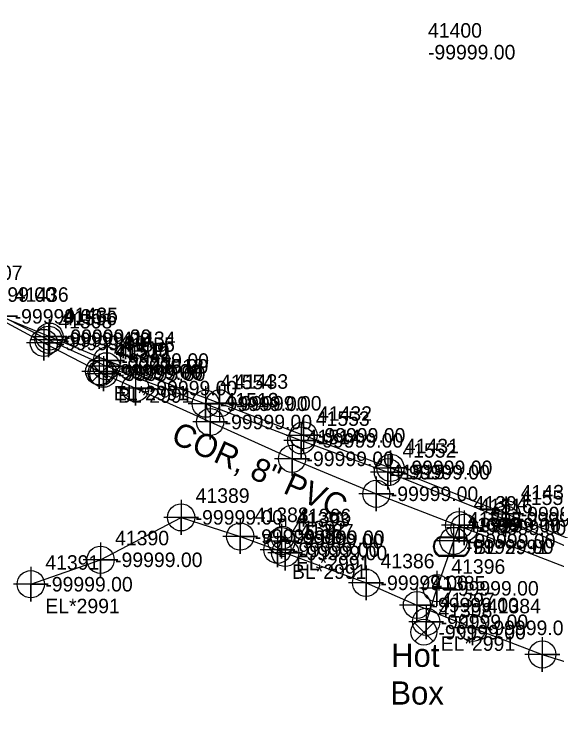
# Model space of a CAD drawing. Extents: x 2083698 to 2094313, y 743246 to 752873.
# Drawn here: x 2091391.9 to 2091485.3, y 744015.4 to 744139.8 of the extents above; entities that cross this region are included whole.
import ezdxf

# ---------------------------------------------------------------- set-up
doc = ezdxf.new("R2010")
doc.units = 0
for name, color, linetype in [('COGO Default Chain', 7, 'Continuous'), ('COGO Default Curve', 7, 'Continuous'), ('COGO Default Point Number', 7, 'Continuous'), ('Default Symbol CELL', 7, 'Continuous'), ('Default Symbol Cogo Comment', 7, 'Continuous'), ('Default Symbol Cogo Number', 7, 'Continuous'), ('Exist Guardrail', 7, 'Continuous'), ('Exist Property Line', 7, 'Continuous'), ('Exist Property Line Leader', 7, 'Continuous'), ('Exist Right of Way Easement Line Leader', 7, 'Continuous'), ('Exist Right of Way Easement Line Text', 7, 'Continuous'), ('Exist Right of Way Line', 7, 'Continuous'), ('Exist Right of Way Width CELL', 7, 'Continuous'), ('Exist Roads EOP', 7, 'Continuous'), ('Exist Roads EOP Leader', 7, 'Continuous'), ('Exist Roads EOP Text', 7, 'Continuous'), ('Exist Utilities Gas UG Line SUE LOS B', 7, 'Continuous'), ('Exist Utilities Other Pole CELL', 7, 'Continuous'), ('Exist Utilities Power Joint Use Telephone Cogo Elevation', 7, 'Continuous'), ('Exist Utilities Power Joint Use Telephone Cogo Number', 7, 'Continuous'), ('Exist Utilities TV UG Cable SUE LOS B', 7, 'Continuous'), ('Exist Utilities Water UG Line SUE LOS B', 7, 'Continuous'), ('Exist Utilities Water UG Line SUE LOS B Text', 7, 'Continuous'), ('Exist Utilities Water Valve Text', 7, 'Continuous'), ('Old_Level_20', 7, 'Continuous'), ('Raster_Level_1', 7, 'Continuous')]:
    doc.layers.add(name, color=color, linetype=linetype)

msp = doc.modelspace()

# ---------------------------------------------------------------- linework, layer by layer
at = {"layer": 'COGO Default Curve'}
for points in [[(2091386.41, 744087.81), (2091392.41, 744087.81), (2091389.41, 744087.81), (2091389.41, 744090.81), (2091389.41, 744084.81)], [(2091394.9, 744084.31), (2091400.9, 744084.31), (2091397.9, 744084.31), (2091397.9, 744087.31), (2091397.9, 744081.31)], [(2091404.82, 744080.19), (2091410.82, 744080.19), (2091407.82, 744080.19), (2091407.82, 744083.19), (2091407.82, 744077.19)], [(2091424.22, 744072.83), (2091430.22, 744072.83), (2091427.22, 744072.83), (2091427.22, 744075.83), (2091427.22, 744069.83)], [(2091438.66, 744067.31), (2091444.66, 744067.31), (2091441.66, 744067.31), (2091441.66, 744070.31), (2091441.66, 744064.31)], [(2091453.64, 744061.71), (2091459.64, 744061.71), (2091456.64, 744061.71), (2091456.64, 744064.71), (2091456.64, 744058.71)], [(2091473.59, 744053.76), (2091479.59, 744053.76), (2091476.59, 744053.76), (2091476.59, 744056.76), (2091476.59, 744050.76)]]:
    msp.add_lwpolyline(points, dxfattribs=at)
for centre in [(2091397.9, 744084.31), (2091407.82, 744080.19), (2091427.22, 744072.83), (2091441.66, 744067.31), (2091456.64, 744061.71), (2091476.59, 744053.76)]:
    msp.add_circle(centre, 2.34, dxfattribs=at)
at = {"layer": 'COGO Default Point Number'}
for points in [[(2091396.94, 744086.22), (2091396.94, 744080.22), (2091396.94, 744083.22), (2091399.94, 744083.22), (2091393.94, 744083.22)], [(2091406.48, 744081.33), (2091406.48, 744075.33), (2091406.48, 744078.33), (2091409.48, 744078.33), (2091403.48, 744078.33)], [(2091407.21, 744080.92), (2091407.21, 744074.92), (2091407.21, 744077.92), (2091410.21, 744077.92), (2091404.21, 744077.92)], [(2091412.7, 744078.45), (2091412.7, 744072.45), (2091412.7, 744075.45), (2091415.7, 744075.45), (2091409.7, 744075.45)], [(2091425.58, 744072.61), (2091425.58, 744066.61), (2091425.58, 744069.61), (2091428.58, 744069.61), (2091422.58, 744069.61)], [(2091439.69, 744066.26), (2091439.69, 744060.26), (2091439.69, 744063.26), (2091442.69, 744063.26), (2091436.69, 744063.26)], [(2091454.21, 744060.24), (2091454.21, 744054.24), (2091454.21, 744057.24), (2091457.21, 744057.24), (2091451.21, 744057.24)], [(2091420.58, 744056.18), (2091420.58, 744050.18), (2091420.58, 744053.18), (2091423.58, 744053.18), (2091417.58, 744053.18)], [(2091468.46, 744054.84), (2091468.46, 744048.84), (2091468.46, 744051.84), (2091471.46, 744051.84), (2091465.46, 744051.84)], [(2091469.37, 744054.39), (2091469.37, 744048.39), (2091469.37, 744051.39), (2091472.37, 744051.39), (2091466.37, 744051.39)], [(2091430.76, 744052.87), (2091430.76, 744046.87), (2091430.76, 744049.87), (2091433.76, 744049.87), (2091427.76, 744049.87)], [(2091437.86, 744052.08), (2091437.86, 744046.08), (2091437.86, 744049.08), (2091440.86, 744049.08), (2091434.86, 744049.08)], [(2091467.51, 744052.12), (2091467.51, 744046.12), (2091467.51, 744049.12), (2091470.51, 744049.12), (2091464.51, 744049.12)], [(2091437.18, 744050.59), (2091437.18, 744044.59), (2091437.18, 744047.59), (2091440.18, 744047.59), (2091434.18, 744047.59)], [(2091438.52, 744050.05), (2091438.52, 744044.05), (2091438.52, 744047.05), (2091441.52, 744047.05), (2091435.52, 744047.05)], [(2091406.71, 744048.87), (2091406.71, 744042.87), (2091406.71, 744045.87), (2091409.71, 744045.87), (2091403.71, 744045.87)], [(2091394.69, 744044.66), (2091394.69, 744038.66), (2091394.69, 744041.66), (2091397.69, 744041.66), (2091391.69, 744041.66)], [(2091452.44, 744044.9), (2091452.44, 744038.9), (2091452.44, 744041.9), (2091455.44, 744041.9), (2091449.44, 744041.9)], [(2091464.63, 744043.96), (2091464.63, 744037.96), (2091464.63, 744040.96), (2091467.63, 744040.96), (2091461.63, 744040.96)], [(2091461.21, 744041.08), (2091461.21, 744035.08), (2091461.21, 744038.08), (2091464.21, 744038.08), (2091458.21, 744038.08)], [(2091462.8, 744038.19), (2091462.8, 744032.19), (2091462.8, 744035.19), (2091465.8, 744035.19), (2091459.8, 744035.19)], [(2091470.76, 744037.15), (2091470.76, 744031.15), (2091470.76, 744034.15), (2091473.76, 744034.15), (2091467.76, 744034.15)], [(2091482.8, 744032.57), (2091482.8, 744026.57), (2091482.8, 744029.57), (2091485.8, 744029.57), (2091479.8, 744029.57)]]:
    msp.add_lwpolyline(points, dxfattribs=at)
for centre in [(2091396.94, 744083.22), (2091406.48, 744078.33), (2091407.21, 744077.92), (2091412.7, 744075.45), (2091425.58, 744069.61), (2091439.69, 744063.26), (2091454.21, 744057.24), (2091420.58, 744053.18), (2091468.46, 744051.84), (2091469.37, 744051.39), (2091430.76, 744049.87), (2091437.86, 744049.08), (2091467.51, 744049.12), (2091437.18, 744047.59), (2091438.52, 744047.05), (2091406.71, 744045.87), (2091452.44, 744041.9), (2091394.69, 744041.66), (2091464.63, 744040.96), (2091461.21, 744038.08), (2091462.8, 744035.19), (2091470.76, 744034.15), (2091482.8, 744029.57)]:
    msp.add_circle(centre, 2.34, dxfattribs=at)
at = {"layer": 'Exist Guardrail'}
msp.add_line((2091467.19, 744048.15), (2091467.19, 744048.15), dxfattribs=at)
for points in [[(2091465.15, 744049.85), (2091469.23, 744049.85)], [(2091465.15, 744049.71), (2091469.23, 744049.71)], [(2091469.23, 744046.59), (2091465.13, 744046.59)], [(2091469.23, 744046.45), (2091465.13, 744046.45)]]:
    msp.add_lwpolyline(points, dxfattribs=at)
for centre, radius, start, end in [((2091465.88, 744048.14), 1.86, 113.178, 245.9794), ((2091465.89, 744048.14), 1.73, 115.3009, 243.7824), ((2091468.48, 744048.15), 1.86, 293.6483, 66.3084), ((2091468.49, 744048.15), 1.73, 295.1272, 64.8728)]:
    msp.add_arc(centre, radius, start, end, dxfattribs=at)
at = {"layer": 'Exist Property Line Leader'}
for points in [[(2091397.73, 744086.77), (2091397.73, 744080.77), (2091397.73, 744083.77), (2091400.73, 744083.77), (2091394.73, 744083.77)], [(2091407.71, 744082.2), (2091407.71, 744076.2), (2091407.71, 744079.2), (2091410.71, 744079.2), (2091404.71, 744079.2)], [(2091424.81, 744075.75), (2091424.81, 744069.75), (2091424.81, 744072.75), (2091427.81, 744072.75), (2091421.81, 744072.75)], [(2091441.28, 744069.44), (2091441.28, 744063.44), (2091441.28, 744066.44), (2091444.28, 744066.44), (2091438.28, 744066.44)], [(2091456.21, 744063.96), (2091456.21, 744057.96), (2091456.21, 744060.96), (2091459.21, 744060.96), (2091453.21, 744060.96)], [(2091476.48, 744055.81), (2091476.48, 744049.81), (2091476.48, 744052.81), (2091479.48, 744052.81), (2091473.48, 744052.81)]]:
    msp.add_lwpolyline(points, dxfattribs=at)
for centre in [(2091397.73, 744083.77), (2091407.71, 744079.2), (2091424.81, 744072.75), (2091441.28, 744066.44), (2091456.21, 744060.96), (2091476.48, 744052.81)]:
    msp.add_circle(centre, 2.34, dxfattribs=at)
at = {"layer": 'Exist Roads EOP'}
for points in [[(2091408.36, 744079.65), (2091405.21, 744076.5), (2091406.79, 744078.08), (2091408.36, 744076.5), (2091405.21, 744079.65)], [(2091463.99, 744034.98), (2091460.84, 744031.83), (2091462.41, 744033.41), (2091463.99, 744031.83), (2091460.84, 744034.98)]]:
    msp.add_lwpolyline(points, dxfattribs=at)
for centre in [(2091406.79, 744078.08), (2091462.41, 744033.41)]:
    msp.add_circle(centre, 2.23, dxfattribs=at)
at = {"layer": 'Exist Utilities Gas UG Line SUE LOS B'}
msp.add_lwpolyline([(2091275.94, 744155.68), (2091302.73, 744130.75), (2091318.38, 744121.54), (2091327.13, 744117.34), (2091336.38, 744112.55), (2091345.74, 744107.55), (2091364.14, 744098.83), (2091374.14, 744093.82), (2091389.41, 744087.81), (2091397.9, 744084.31), (2091407.82, 744080.19), (2091427.22, 744072.83), (2091441.66, 744067.31), (2091456.64, 744061.71), (2091476.59, 744053.76), (2091491.02, 744048.12), (2091500.33, 744044.21), (2091513.57, 744037.87), (2091528.9, 744031.7), (2091538.22, 744027.97), (2091551.87, 744023.07), (2091568.35, 744016.95)], dxfattribs=at)
at = {"layer": 'Exist Utilities TV UG Cable SUE LOS B'}
msp.add_lwpolyline([(2091298.28, 744127.88), (2091312.57, 744118.37), (2091316.43, 744115.07), (2091324, 744112.24), (2091333.98, 744106.69), (2091346.62, 744099.68), (2091362.52, 744093), (2091364.53, 744092.95), (2091371.85, 744095.99), (2091373.92, 744095.82), (2091397.73, 744083.77), (2091407.71, 744079.2), (2091424.81, 744072.75), (2091441.28, 744066.44), (2091456.21, 744060.96), (2091476.48, 744052.81), (2091490.27, 744046.72), (2091499.71, 744043.29), (2091513.37, 744036.74), (2091528.81, 744030.18), (2091537.87, 744027.13), (2091551.85, 744022.19), (2091567.56, 744016.21)], dxfattribs=at)
at = {"layer": 'Exist Utilities Water UG Line SUE LOS B'}
msp.add_line((2091437.18, 744047.59), (2091437.86, 744049.08), dxfattribs=at)
for points in [[(2091056.21, 744203.11), (2091072.46, 744200.56), (2091092.4, 744197.14), (2091113.77, 744193.57), (2091124.23, 744191.81), (2091152.88, 744187.38), (2091165.46, 744185.56), (2091179.47, 744183.15), (2091207.4, 744177.39), (2091219.19, 744174.43), (2091233.72, 744170.14), (2091249.57, 744162.32), (2091257.28, 744159.64), (2091263.15, 744157.74), (2091271.33, 744153.94), (2091292.63, 744141.58), (2091305.14, 744134.57), (2091320.06, 744127.37), (2091329.49, 744121.28), (2091347.09, 744109.48), (2091365.5, 744100.66), (2091381.46, 744091.56), (2091396.94, 744083.22), (2091406.48, 744078.33)], [(2091407.21, 744077.92), (2091412.7, 744075.45), (2091425.58, 744069.61), (2091439.69, 744063.26), (2091454.21, 744057.24), (2091469.37, 744051.39), (2091489.36, 744043.6), (2091496.48, 744040.81), (2091513.15, 744035.08), (2091526.62, 744030.28), (2091537.83, 744026.65), (2091551.42, 744021.27), (2091566.51, 744014.75), (2091578.38, 744009.86), (2091588.84, 744005.74), (2091599.06, 744002.21), (2091615.79, 743995.67), (2091635.34, 743988.1), (2091663.48, 743976.23), (2091680.48, 743968.35), (2091693.9, 743960.86), (2091715.35, 743950.49)], [(2091394.69, 744041.66), (2091406.71, 744045.87), (2091420.58, 744053.18), (2091430.76, 744049.87), (2091438.52, 744047.05), (2091452.44, 744041.9), (2091461.21, 744038.08), (2091470.76, 744034.15), (2091482.8, 744029.57), (2091496.29, 744025.34), (2091509.04, 744021.19), (2091511.03, 744020.3), (2091515.59, 744017.83)], [(2091468.46, 744051.84), (2091467.51, 744049.12), (2091464.63, 744040.96), (2091462.8, 744035.19)]]:
    msp.add_lwpolyline(points, dxfattribs=at)
at = {"layer": 'Raster_Level_1'}
msp.add_line((2091438.08, 744049.67), (2091438.08, 744049.67), dxfattribs=at)
for points in [[(2091437.57, 744051.58), (2091437.57, 744052.87), (2091438.59, 744052.87), (2091438.59, 744051.55)], [(2091436.17, 744050.18), (2091434.88, 744050.18), (2091434.88, 744049.15), (2091436.17, 744049.15)], [(2091437.57, 744047.75), (2091437.57, 744046.47), (2091438.59, 744046.47), (2091438.59, 744047.78)]]:
    msp.add_lwpolyline(points, dxfattribs=at)
for radius in [1.98, 0.243]:
    msp.add_circle((2091438.08, 744049.67), radius, dxfattribs=at)

# ---------------------------------------------------------------- texts
at = {"layer": 'COGO Default Chain'}
for p in [(2091391.91, 744086.56), (2091400.4, 744083.06), (2091410.32, 744078.94), (2091429.72, 744071.58), (2091444.16, 744066.06), (2091459.14, 744060.46), (2091479.09, 744052.51)]:
    msp.add_text('-99999.00', height=2.5, dxfattribs=at).set_placement(p)
at = {"layer": 'Default Symbol CELL'}
for s, p in [('41556', (2091400.23, 744086.27)), ('41555', (2091410.21, 744081.7)), ('41554', (2091427.31, 744075.25)), ('41553', (2091443.78, 744068.94)), ('41552', (2091458.71, 744063.46)), ('41551', (2091478.98, 744055.31))]:
    msp.add_text(s, height=2.5, dxfattribs=at).set_placement(p)
at = {"layer": 'Default Symbol Cogo Comment'}
msp.add_text('-99999.00', height=2.5, dxfattribs=at).set_placement((2091469.69, 744046.9))
at = {"layer": 'Default Symbol Cogo Number'}
for p in [(2091400.23, 744082.52), (2091410.21, 744077.95), (2091427.31, 744071.5), (2091443.78, 744065.19), (2091458.71, 744059.71), (2091478.98, 744051.56)]:
    msp.add_text('-99999.00', height=2.5, dxfattribs=at).set_placement(p)
at = {"layer": 'Exist Property Line'}
for p in [(2091383.96, 744090.31), (2091399.44, 744081.97), (2091408.98, 744077.08), (2091409.71, 744076.67), (2091415.2, 744074.2), (2091428.08, 744068.36), (2091442.19, 744062.01), (2091456.71, 744055.99), (2091423.08, 744051.93), (2091470.96, 744050.59), (2091471.87, 744050.14), (2091433.26, 744048.62), (2091470.01, 744047.87), (2091440.36, 744047.83), (2091439.68, 744046.34), (2091441.02, 744045.8), (2091409.21, 744044.62), (2091397.19, 744040.41), (2091454.94, 744040.65), (2091467.13, 744039.71), (2091463.71, 744036.83), (2091465.3, 744033.94), (2091473.26, 744032.9)]:
    msp.add_text('-99999.00', height=2.5, dxfattribs=at).set_placement(p)
at = {"layer": 'Exist Right of Way Easement Line Leader'}
msp.add_text('-99999.00', height=2.5, dxfattribs=at).set_placement((2091440.58, 744048.42))
at = {"layer": 'Exist Right of Way Easement Line Text'}
msp.add_text('41366', height=2.5, dxfattribs=at).set_placement((2091440.58, 744052.17))
at = {"layer": 'Exist Right of Way Line'}
for s, p in [('41507', (2091383.96, 744094.06)), ('41508', (2091399.44, 744085.72)), ('41509', (2091408.98, 744080.83)), ('41511', (2091409.71, 744080.42)), ('41512', (2091415.2, 744077.95)), ('41513', (2091428.08, 744072.11)), ('41514', (2091442.19, 744065.76)), ('41515', (2091456.71, 744059.74)), ('41389', (2091423.08, 744055.68)), ('41394', (2091470.96, 744054.34)), ('41516', (2091471.87, 744053.89)), ('41388', (2091433.26, 744052.37)), ('41393', (2091440.36, 744051.58)), ('41395', (2091470.01, 744051.62)), ('41392', (2091439.68, 744050.09)), ('41387', (2091441.02, 744049.55)), ('41390', (2091409.21, 744048.37)), ('41391', (2091397.19, 744044.16)), ('41386', (2091454.94, 744044.4)), ('41396', (2091467.13, 744043.46)), ('41385', (2091463.71, 744040.58)), ('41397', (2091465.3, 744037.69)), ('41384', (2091473.26, 744036.65))]:
    msp.add_text(s, height=2.5, dxfattribs=at).set_placement(p)
at = {"layer": 'Exist Right of Way Width CELL'}
for s, p in [('EL*2991', (2091408.98, 744073.33)), ('BL*2991', (2091409.71, 744072.92)), ('BL*2991', (2091470.96, 744046.84)), ('EL*2991', (2091440.36, 744044.08)), ('BL*2991', (2091439.68, 744042.59)), ('EL*2991', (2091397.19, 744036.66)), ('EL*2991', (2091465.3, 744030.19))]:
    msp.add_text(s, height=2.5, dxfattribs=at).set_placement(p)
at = {"layer": 'Exist Roads EOP Leader'}
for p in [(2091409.29, 744076.83), (2091464.91, 744032.16)]:
    msp.add_text('-99999.00', height=2.5, dxfattribs=at).set_placement(p)
at = {"layer": 'Exist Roads EOP Text'}
for s, p in [('41510', (2091409.29, 744080.58)), ('41398', (2091464.91, 744035.91))]:
    msp.add_text(s, height=2.5, dxfattribs=at).set_placement(p)
at = {"layer": 'Exist Utilities Other Pole CELL'}
msp.add_text('41399', height=2.5, dxfattribs=at).set_placement((2091469.69, 744050.65))
at = {"layer": 'Exist Utilities Power Joint Use Telephone Cogo Elevation'}
msp.add_text('-99999.00', height=2.5, dxfattribs=at).set_placement((2091463.11, 744132.06))
at = {"layer": 'Exist Utilities Power Joint Use Telephone Cogo Number'}
msp.add_text('41400', height=2.5, dxfattribs=at).set_placement((2091463.11, 744135.81))
at = {"layer": 'Exist Utilities Water UG Line SUE LOS B Text'}
msp.add_text('COR, 8" PVC', height=4, rotation=335.7736, dxfattribs=at).set_placement((2091418.62, 744066.16))
at = {"layer": 'Exist Utilities Water Valve Text'}
for s, p in [('Hot', (2091456.76, 744027.43)), ('Box', (2091456.63, 744020.93))]:
    msp.add_text(s, height=4, dxfattribs=at).set_placement(p)
at = {"layer": 'Old_Level_20'}
for s, p in [('41436', (2091391.91, 744090.31)), ('41435', (2091400.4, 744086.81)), ('41434', (2091410.32, 744082.69)), ('41433', (2091429.72, 744075.33)), ('41432', (2091444.16, 744069.81)), ('41431', (2091459.14, 744064.21)), ('41430', (2091479.09, 744056.26))]:
    msp.add_text(s, height=2.5, dxfattribs=at).set_placement(p)

doc.saveas('drawing.dxf')
